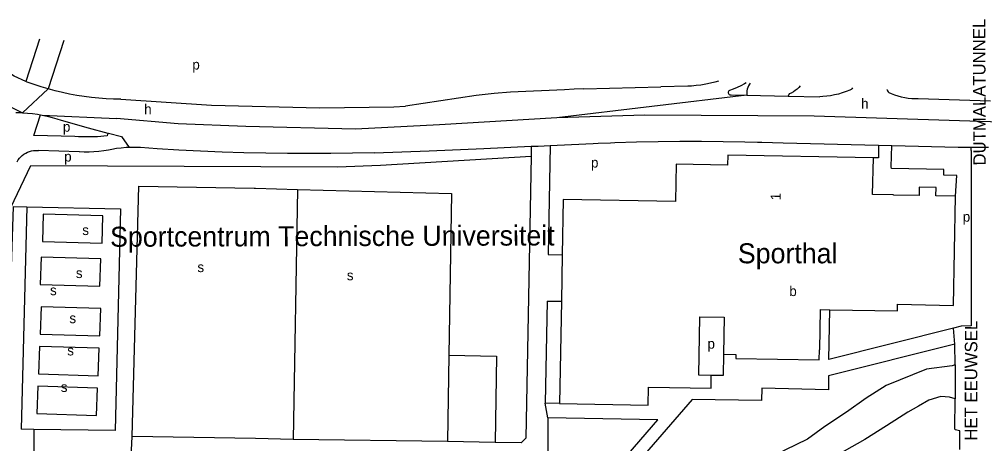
# Model space of a CAD drawing. Extents: x 161494 to 163033, y 383688 to 384862.
# Drawn here: x 161805.5 to 162191.5, y 384692.8 to 384862.5 of the extents above; entities that cross this region are included whole.
import ezdxf

# ---------------------------------------------------------------- set-up
doc = ezdxf.new("R2010")
doc.units = 0
for name, color, linetype in [('BLT_Basislijn', 7, 'Continuous'), ('BLT_Bebouwing', 7, 'Continuous'), ('BLT_Bebouwing_beschrifting', 7, 'Continuous'), ('BLT_Centroide', 7, 'Continuous'), ('BLT_Huisnummer', 7, 'Continuous'), ('BLT_Straatnaam', 7, 'Continuous'), ('BLT_Terrein_beschrifting', 7, 'Continuous'), ('BLT_Vlakafsluiter', 7, 'Continuous')]:
    doc.layers.add(name, color=color, linetype=linetype)

msp = doc.modelspace()

# ---------------------------------------------------------------- linework, layer by layer
at = {"layer": 'BLT_Basislijn'}
for p, q in [((161813.53, 384854.59), (161808.06, 384837.6)), ((161823.31, 384853.98), (161816.99, 384834.64)), ((162031.24, 384834.67), (162062.01, 384835.53)), ((162072.87, 384835.76), (162062.01, 384835.53)), ((162090.12, 384832.25), (162096.45, 384832.12)), ((162096.45, 384832.12), (162112.89, 384831.8)), ((162113.36, 384832.64), (162112.89, 384831.8)), ((162112.89, 384831.8), (162125.67, 384831.55)), ((162164.95, 384830.77), (162193.87, 384829.95)), ((161814.03, 384824.28), (161814.59, 384824.18)), ((161814.59, 384824.18), (161814.71, 384824.18)), ((161846.44, 384815.6), (161849.4, 384811.23)), ((162010.25, 384811.69), (162010.17, 384807.78)), ((162017.8, 384812.04), (162016.97, 384768.45)), ((162017.8, 384812.04), (162026.38, 384812.45)), ((162036.95, 384812.93), (162041.93, 384813.13)), ((162100.69, 384813.4), (162101.5, 384813.38)), ((162101.5, 384813.38), (162102.42, 384813.35)), ((162102.42, 384813.35), (162110.96, 384813.14)), ((162110.96, 384813.14), (162149.12, 384812.11)), ((162149.12, 384812.11), (162154.38, 384811.96)), ((162154.38, 384811.96), (162180.88, 384811.41)), ((162180.88, 384811.41), (162186.14, 384811.38)), ((161829.4, 384809.47), (161813.17, 384809.96)), ((161784.28, 384750), (161810.11, 384804.01)), ((161916.76, 384794.48), (161914.99, 384694.39)), ((161916.76, 384794.48), (161978.39, 384792.89)), ((161978.39, 384792.89), (161977.26, 384728.14)), ((161808.49, 384787.5), (161806.23, 384698.56)), ((162016.97, 384768.45), (162022.63, 384768.34)), ((162016.61, 384749.77), (162015.83, 384708.96)), ((162016.61, 384749.77), (162022.28, 384749.77)), ((162179.66, 384732.5), (162179.05, 384738.94)), ((162179.66, 384732.5), (162129.11, 384719.89)), ((162179.7, 384724.34), (162179.66, 384732.5)), ((161977.26, 384728.14), (161976.75, 384693.68)), ((161977.26, 384728.14), (161996.29, 384727.78)), ((161996.29, 384727.78), (161995.77, 384693.29)), ((162179.7, 384724.34), (162179.7, 384710.65)), ((162021.51, 384708.88), (162015.83, 384708.96)), ((162016.89, 384703.11), (162015.83, 384708.96)), ((162016.89, 384703.11), (162016.86, 384687.59)), ((161811.31, 384698.49), (161806.23, 384698.56)), ((161976.75, 384693.68), (161914.99, 384694.39)), ((161995.77, 384693.29), (161976.75, 384693.68))]:
    msp.add_line(p, q, dxfattribs=at)
for points in [[(161808.06, 384837.6), (161803.46, 384839.8), (161799.38, 384842.4)], [(161816.99, 384834.64), (161814.2, 384835.48), (161811.39, 384836.4), (161808.62, 384837.39), (161808.06, 384837.6)], [(162085.03, 384837.75), (162083.67, 384837.35), (162081.83, 384836.89), (162079.97, 384836.5), (162078.09, 384836.2), (162076.2, 384835.97), (162074.31, 384835.82), (162072.87, 384835.76)], [(162096.15, 384837.06), (162095.54, 384836.69), (162094.05, 384835.9), (162092.53, 384835.17), (162090.98, 384834.52), (162089.51, 384833.99)], [(161846.15, 384830.5), (161843.2, 384830.55), (161840.25, 384830.69), (161837.31, 384830.91), (161834.38, 384831.2), (161831.45, 384831.58), (161828.53, 384832.03), (161825.63, 384832.56), (161822.74, 384833.18), (161819.88, 384833.86), (161816.99, 384834.64)], [(162001.87, 384833.3), (161995.41, 384832.86), (161988.23, 384832.01), (161959.92, 384827.7)], [(162031.24, 384834.67), (162027.4, 384834.52), (162023.57, 384834.29), (162001.87, 384833.3)], [(162089.51, 384833.99), (162089.29, 384833.83), (162089.12, 384833.62), (162089.02, 384833.37), (162088.99, 384833.1), (162089.05, 384832.83), (162089.18, 384832.6), (162089.37, 384832.41), (162089.61, 384832.28), (162089.88, 384832.23), (162090.12, 384832.25)], [(162097.75, 384836.96), (162097.45, 384836.54), (162097.09, 384835.91), (162096.8, 384835.24), (162096.59, 384834.55), (162096.46, 384833.83), (162096.4, 384833.11), (162096.43, 384832.38), (162096.45, 384832.12)], [(162117.79, 384835.87), (162117.2, 384835.21), (162116.53, 384834.56), (162115.8, 384833.98), (162115.03, 384833.46), (162114.21, 384833.01), (162113.36, 384832.64)], [(162137.57, 384834.16), (162136.09, 384833.56), (162134.59, 384833.04), (162133.05, 384832.6), (162131.5, 384832.23), (162129.93, 384831.94), (162128.35, 384831.73), (162126.76, 384831.6), (162125.67, 384831.55)], [(162138.65, 384835.03), (162138.65, 384835.03), (162138.43, 384834.72), (162138.15, 384834.46), (162137.82, 384834.26), (162137.57, 384834.16)], [(162152.45, 384834.48), (162152.5, 384834.24), (162152.65, 384833.88), (162152.88, 384833.55), (162153.17, 384833.27), (162153.5, 384833.06), (162153.87, 384832.91), (162154.17, 384832.86)], [(161846.15, 384830.5), (161882.43, 384828.17), (161925.7, 384827.13), (161955.24, 384827.48), (161959.92, 384827.7)], [(162154.17, 384832.86), (162155.48, 384832.33), (162156.81, 384831.87), (162158.17, 384831.49), (162159.54, 384831.19), (162160.93, 384830.97), (162162.34, 384830.83), (162163.74, 384830.76), (162164.95, 384830.77)], [(161806.74, 384825.04), (161805.67, 384825.11), (161804.59, 384825.1), (161804.12, 384825.06)], [(161806.74, 384825.04), (161808.74, 384824.94), (161810.74, 384824.76), (161812.73, 384824.5), (161814.03, 384824.28)], [(161827.71, 384815.6), (161811.33, 384816.03), (161814.03, 384824.28)], [(161814.71, 384824.18), (161816.68, 384823.74), (161818.62, 384823.25), (161820.55, 384822.68), (161822.25, 384822.1)], [(161822.25, 384822.1), (161833.09, 384819.06), (161840.93, 384816.98)], [(162020.49, 384823.11), (161973.58, 384820.32), (161939.88, 384818.59), (161896.11, 384819.63), (161869.01, 384820.67), (161844.34, 384822.76)], [(162210.54, 384821.02), (162123.33, 384823.8), (162055.58, 384824.15), (162020.49, 384823.11)], [(161836.82, 384815.51), (161834.26, 384815.43), (161831.69, 384815.43), (161829.13, 384815.52), (161827.71, 384815.6)], [(161840.93, 384816.98), (161840.63, 384815.94), (161836.82, 384815.51)], [(161840.93, 384816.98), (161841.24, 384816.9), (161846.44, 384815.6)], [(161804.65, 384805.55), (161805.07, 384806.26), (161805.56, 384806.92), (161806.11, 384807.53), (161806.71, 384808.08), (161807.37, 384808.58), (161808.07, 384809), (161808.81, 384809.36), (161809.59, 384809.64), (161810.38, 384809.85), (161811.19, 384809.98), (161812.01, 384810.03), (161812.83, 384809.99), (161813.17, 384809.96)], [(161841.19, 384810.16), (161839.26, 384809.84), (161837.33, 384809.61), (161835.38, 384809.45), (161833.43, 384809.37), (161831.48, 384809.37), (161829.53, 384809.46), (161829.4, 384809.47)], [(161849.4, 384811.23), (161848.23, 384811.17), (161846.31, 384811.01), (161844.39, 384810.76), (161842.49, 384810.43), (161841.19, 384810.16)], [(161854.02, 384811.2), (161852.09, 384811.27), (161850.16, 384811.26), (161849.4, 384811.23)], [(161947.49, 384809.12), (161938.8, 384808.92), (161930.11, 384808.8), (161921.42, 384808.77), (161912.73, 384808.81), (161904.04, 384808.93), (161895.36, 384809.14), (161886.67, 384809.42), (161877.99, 384809.78), (161869.31, 384810.22), (161860.64, 384810.75), (161854.02, 384811.2)], [(161947.49, 384809.12), (161969.34, 384809.94), (161991.2, 384810.83), (162010.25, 384811.69)], [(162010.25, 384811.69), (162013.05, 384811.81), (162017.8, 384812.04)], [(162026.38, 384812.45), (162035.04, 384812.86), (162036.95, 384812.93)], [(162041.93, 384813.13), (162043.69, 384813.2), (162052.35, 384813.45), (162061.02, 384813.62), (162069.68, 384813.72), (162078.34, 384813.73), (162087, 384813.67), (162095.67, 384813.52), (162100.69, 384813.4)], [(162149.12, 384812.11), (162149.01, 384807.08), (162147.01, 384807.12)], [(162179.88, 384791.7), (162180.33, 384800.05), (162175.18, 384800.14), (162175.22, 384802.38), (162154.3, 384802.77), (162154.18, 384803.43), (162154.38, 384811.96)], [(162186.1, 384810), (162186.08, 384739.9), (162182.17, 384739.79), (162179.05, 384738.94)], [(162186.1, 384810), (162186.14, 384811.38)], [(162186.14, 384811.38), (162188.96, 384811.37), (162193, 384811.31)], [(161810.11, 384804.01), (161932.73, 384803.48), (161949.97, 384804.11), (162010.17, 384807.78)], [(162010.17, 384807.78), (162008, 384694.94), (162006.16, 384693.07), (161995.77, 384693.29)], [(161850.61, 384695.61), (161853.25, 384795.78), (161899.48, 384794.92), (161900, 384794.91), (161916.76, 384794.48)], [(161800.97, 384719.21), (161803.24, 384787.61), (161808.49, 384787.5)], [(161808.49, 384787.5), (161846.03, 384786.72), (161843.82, 384698.02), (161811.31, 384698.49)], [(161838.93, 384783.88), (161815.08, 384784.62), (161814.74, 384773.66), (161838.59, 384772.91), (161838.93, 384783.88)], [(161838.05, 384766.67), (161814.2, 384767.41), (161813.85, 384756.45), (161837.71, 384755.7), (161838.05, 384766.67)], [(161838.05, 384746.81), (161814.2, 384747.55), (161813.85, 384736.59), (161837.71, 384735.84), (161838.05, 384746.81)], [(162179.05, 384738.94), (162129.27, 384726.43), (162129.63, 384746.34)], [(161837.39, 384730.92), (161813.54, 384731.66), (161813.19, 384720.7), (161837.05, 384719.96), (161837.39, 384730.92)], [(162087.13, 384728.53), (162086.99, 384720.03), (162082.18, 384720.09)], [(162179.7, 384724.34), (162178.5, 384723.83), (162168.2, 384722.51), (162152.1, 384716.01), (162148.13, 384713.48)], [(162129.11, 384719.89), (162129.02, 384714.31), (162102.45, 384714.98), (162102.34, 384709.99), (162074.52, 384710.46), (162037.26, 384667.41)], [(161836.73, 384715.03), (161812.87, 384715.78), (161812.53, 384704.82), (161836.38, 384704.07), (161836.73, 384715.03)], [(162148.13, 384713.48), (162144.15, 384710.95), (162136.26, 384705.43), (162127.66, 384699.69), (162120.65, 384694.55), (162111.65, 384690.15), (162102.89, 384685.49)], [(162179.7, 384710.65), (162177.51, 384711.43), (162173.99, 384711.62), (162169.26, 384710.13), (162165.05, 384707.78), (162160.85, 384705.43), (162152.23, 384699.94)], [(162181.58, 384690.47), (162181.57, 384697.92), (162179.73, 384698.26), (162179.65, 384698.65), (162179.7, 384710.65)], [(162033.72, 384670.96), (162060.84, 384702.3), (162016.89, 384703.11)], [(161811.31, 384698.49), (161811.31, 384683.25), (161820.02, 384683.07)], [(162152.23, 384699.94), (162143.61, 384694.45), (162135.39, 384689.81), (162127.17, 384685.16), (162118.75, 384680.11), (162106.58, 384673.66)], [(161820.02, 384683.07), (161850.02, 384682.12), (161850.61, 384695.61)], [(161914.99, 384694.39), (161900, 384694.8), (161850.61, 384695.61)]]:
    msp.add_lwpolyline(points, dxfattribs=at)
at = {"layer": 'BLT_Bebouwing'}
for p, q in [((162147.01, 384807.12), (162088.81, 384808.18)), ((162023.04, 384790.39), (162022.63, 384768.34)), ((162022.63, 384768.34), (162022.28, 384749.77)), ((162022.28, 384749.77), (162021.51, 384708.88)), ((162129.63, 384746.34), (162156.62, 384745.83))]:
    msp.add_line(p, q, dxfattribs=at)
for points in [[(162088.81, 384808.18), (162088.75, 384804.18), (162068.16, 384804.56)], [(162179.88, 384791.7), (162172.01, 384791.85), (162172.07, 384795.17), (162165.35, 384795.3), (162165.28, 384791.98), (162155.04, 384792.16), (162155.05, 384792.31), (162146.73, 384792.47), (162147.01, 384807.12)], [(162068.16, 384804.56), (162067.88, 384789.57), (162023.04, 384790.39)], [(162156.62, 384745.83), (162156.67, 384748.5), (162179.04, 384748.07), (162179.88, 384791.7)], [(162087.13, 384728.53), (162092.02, 384728.45), (162091.99, 384726.87), (162125.34, 384726.26), (162125.42, 384730.34), (162125.59, 384730.34), (162125.84, 384746.41), (162129.63, 384746.34)], [(162082.18, 384720.09), (162077.18, 384720.17), (162077.63, 384743.53), (162087.39, 384743.36), (162087.13, 384728.53)], [(162021.51, 384708.88), (162056.98, 384708.23), (162057.1, 384715.42), (162082.1, 384714.99), (162082.18, 384720.09)]]:
    msp.add_lwpolyline(points, dxfattribs=at)
at = {"layer": 'BLT_Vlakafsluiter'}
for p, q in [((161783.92, 384836.6), (161806.74, 384825.04)), ((161816.99, 384834.64), (161806.74, 384825.04)), ((162096.45, 384832.12), (162020.49, 384823.11)), ((161814.71, 384824.18), (161844.34, 384822.76))]:
    msp.add_line(p, q, dxfattribs=at)

# ---------------------------------------------------------------- texts
at = {"layer": 'BLT_Bebouwing_beschrifting'}
msp.add_text('Sporthal', height=8, dxfattribs=at).set_placement((162092.83, 384764.9))
at = {"layer": 'BLT_Centroide'}
for s, p in [('p', (161874.71, 384842.4)), ('h', (162142.11, 384826.79)), ('h', (161855.45, 384824.55)), ('p', (161822.95, 384817.54)), ('p', (161823.45, 384805.61)), ('p', (162034.11, 384803.2)), ('p', (162182.76, 384781.53)), ('s', (161830.69, 384776.21)), ('s', (161876.73, 384761.38)), ('s', (161828.12, 384759.01)), ('s', (161936.48, 384758.11)), ('b', (162113.4, 384751.81)), ('s', (161817.8, 384752.14)), ('s', (161825.54, 384740.96)), ('p', (162080.69, 384730.75)), ('s', (161824.68, 384728.06)), ('s', (161822.1, 384713.44))]:
    msp.add_text(s, height=4, dxfattribs=at).set_placement(p)
at = {"layer": 'BLT_Huisnummer'}
msp.add_text('1', height=4, rotation=88.8879, dxfattribs=at).set_placement((162109.94, 384790.1))
at = {"layer": 'BLT_Straatnaam'}
for s, height, rotation, p in [('DUTMALATUNNEL', 5, 90.1963, (162191.98, 384804.02)), ('HET EEUWSEL', 4.9999, 89.9239, (162188.55, 384693.98))]:
    msp.add_text(s, height=height, rotation=rotation, dxfattribs=at).set_placement(p)
at = {"layer": 'BLT_Terrein_beschrifting'}
msp.add_text('Sportcentrum Technische Universiteit', height=8, rotation=0.174, dxfattribs=at).set_placement((161841.82, 384771.51))

doc.saveas('drawing.dxf')
